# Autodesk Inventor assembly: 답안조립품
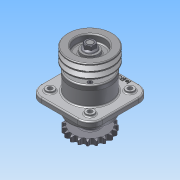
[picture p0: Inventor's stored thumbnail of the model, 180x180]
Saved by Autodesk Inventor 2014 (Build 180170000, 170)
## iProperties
Created: 2015-09
Part Number: 답안조립품
Document SubType Name: Assembly
Designer: study
Author: study
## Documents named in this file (12)
- C:\Users\study\Desktop\450909V1004\답안조립품.iam
- C:\Users\study\Desktop\450909V1004\1-본체.ipt
- C:\Users\study\Desktop\450909V1004\2-커버.ipt
- C:\Users\study\Desktop\450909V1004\3-축.ipt
- C:\Users\study\Desktop\450909V1004\4-V벨트풀리.ipt
- C:\Users\study\Desktop\450909V1004\5-체인 스프로킷.ipt
- C:\Users\study\Desktop\450909V1004\6-베어링 6206.ipt
- C:\Users\study\Desktop\450909V1004\7-부시.ipt
- C:\Users\study\Desktop\450909V1004\8-오일실 30x42.ipt
- C:\Users\study\Desktop\450909V1004\9-M16-너트.ipt
- C:\Users\study\Desktop\450909V1004\10-M6.ipt
- C:\Users\study\Desktop\450909V1004\11-키 6x6.ipt
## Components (23 placed, 11 different names)
1. 1-본체:1
2. 2-커버:1
3. 3-축:1 — 각도:1, 각도:2
4. 4-V벨트풀리:1 — 각도:4
5. 5-체인 스프로킷:1 — 각도:3
6. 6-베어링 6206:1
7. 7-부시:1
8. 8-8-오일실 30x42:1
9. 9-M16 너트:1
10. 11-키 6x6:1 — 각도:2, 각도:3
11. 2-커버:2
12. 6-베어링 6206:2
13. 8-8-오일실 30x42:2
14. 11-키 6x6:2 — 각도:1, 각도:4
15. 9-M16 너트:2
16. 10-M6:1
17. 10-M6:3
18. 10-M6:4
19. 10-M6:5
20. 10-M6:2
21. 10-M6:6
22. 10-M6:7
23. 10-M6:8
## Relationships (4: Angle 4)
- 각도:1 [Angle]: 3-축:1 ↔ 11-키 6x6:2
- 각도:2 [Angle]: 3-축:1 ↔ 11-키 6x6:1
- 각도:3 [Angle]: 5-체인 스프로킷:1 ↔ 11-키 6x6:1
- 각도:4 [Angle]: 4-V벨트풀리:1 ↔ 11-키 6x6:2
